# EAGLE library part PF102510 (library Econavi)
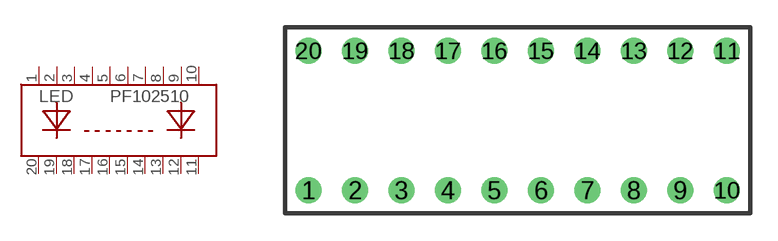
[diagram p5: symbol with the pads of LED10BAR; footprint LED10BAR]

Designator prefix LED

## PF102510  [LED10BAR]
1  A0  pas
2  A1  pas
3  A2  pas
4  A3  pas
5  A4  pas
6  A5  pas
7  A6  pas
8  A7  pas
9  A8  pas
10  A9  pas
11  K9  pas
12  K8  pas
13  K7  pas
14  K6  pas
15  K5  pas
16  K4  pas
17  K3  pas
18  K2  pas
19  K1  pas
20  K0  pas

## Footprint LED10BAR (pad centres in mm)
drill 0.9 round: 1 -10.16,-5.08; 2 -7.62,-5.08; 3 -5.08,-5.08; 4 -2.54,-5.08; 5 0,-5.08; 6 2.54,-5.08; 7 5.08,-5.08; 8 7.62,-5.08; 9 10.16,-5.08; 10 12.7,-5.08; 11 12.7,2.54; 12 10.16,2.54; 13 7.62,2.54; 14 5.08,2.54; 15 2.54,2.54; 16 0,2.54; 17 -2.54,2.54; 18 -5.08,2.54; 19 -7.62,2.54; 20 -10.16,2.54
